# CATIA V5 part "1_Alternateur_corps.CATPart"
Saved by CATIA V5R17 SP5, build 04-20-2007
Part number: 1_Alternateur_corps
Bounding box of the stored display mesh (mm): x -108.985 to 108.985, y -152 to 32, z -108.985 to 108.985
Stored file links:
  C:\Users\Frédéric\Documents\WF\STSCPI 09-11\Projets\Projet multiplicateur eolienne\Maquette eolienne\1_Alternateur_corps.CATPart
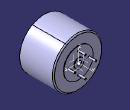
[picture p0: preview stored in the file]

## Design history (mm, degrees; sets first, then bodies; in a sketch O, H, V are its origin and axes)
AxisSystem1: origin (0, 0, 0), X (1, 0, 0), Y (0, 1, 0), Z (0, 0, 1)
Body1 (main body)
  Sketch1 on YZ plane of AxisSystem1, origin (0, 0, 0), H (0, 1, 0), V (0, 0, 1)
    line L1 (0, 0) -> (0, 65)
    line L2 (0, 65) -> (-2, 65)
    line L3 (-2, 65) -> (-2, 109)
    line L4 (-2, 109) -> (-152, 109)
    line L5 (-152, 109) -> (-152, 0)
    line L6 (-152, 0) -> (0, 0)
    length L1 = 65
    distance L4 L6 = 109
    length L4 = 150
    length L2 = 2
    vertical: L1 V, L3 V, L5 V
    horizontal: L2 H, L4 H, L6 H
  Shaft1: profile Sketch1, axis Sketch1.L6, angle 360
  Fillet1: radius 5, on edge [face of Shaft1 from Sketch1.L4 | face of Shaft1 from Sketch1.L3]
  Sketch2 on face of Shaft1 from Sketch1.L1, origin (0, 0, 0), H (-1, 0, 0), V (0, 0, 1)
    circle A1 centre (0, 0) radius 21
    radius A1 = 21
  Pad1: profile Sketch2, direction (0, 1, 0), length 3
  Sketch3 on end face of Pad1, origin (0, 3, 0), H (1, 0, 0), V (0, 0, -1)
    point P1 (0, 0)
  Hole1: placed by Sketch3, at (0, 3, 0) direction (0, -1, 0), diameter 20, depth 60
  Sketch4 on ZX plane of AxisSystem1, origin (0, 0, 0), H (0, 0, 1), V (1, 0, 0)
    circle A1 centre (0, 46) radius 4
    point P1 (0, 46)
    distance P1 H = 46
    radius A1 = 4
    coincidence: P1 V
  Pad2: profile Sketch4, direction (0, 1, 0), length 32
  Chamfer1: length 1, angle 45, on edge [face of Pad2 from Sketch4.A1 | end face of Pad2]
  Thread1: "M8", diameter 8, depth 30, pitch 1.25, on face of Pad2 from Sketch4.A1, from end face of Pad2
  CircPattern1: of Pad2, Sketch4, Chamfer1, Thread1, instances 4, angular step 90, axis from edge [YZ plane of AxisSystem1 | XY plane of AxisSystem1]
